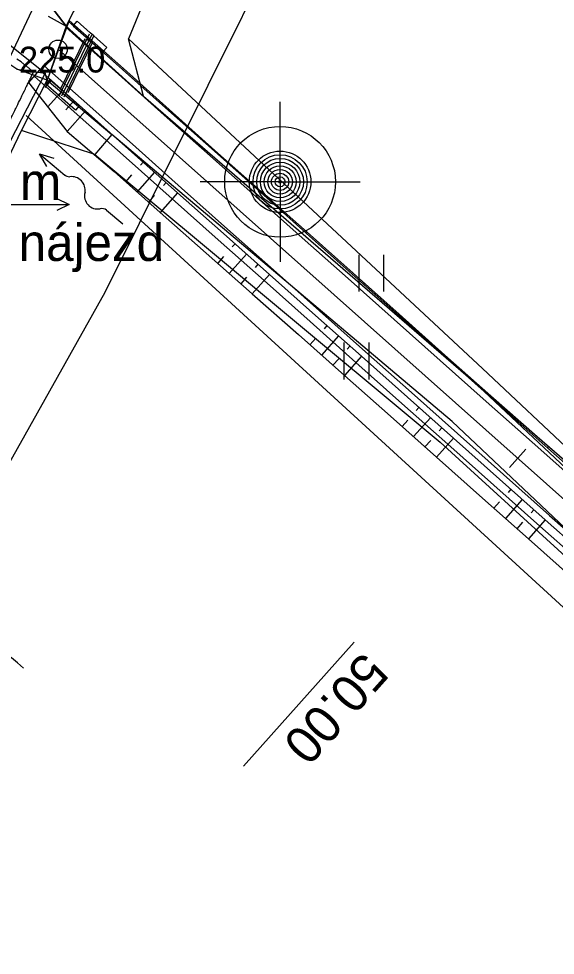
# Model space of a CAD drawing. Extents: x -495905 to -478420, y -1113297 to -1107716.
# Drawn here: x -480961.7 to -480918.1, y -1112652.6 to -1112576.5 of the extents above; entities that cross this region are included whole.
import ezdxf

# ---------------------------------------------------------------- set-up
doc = ezdxf.new("R2010")
doc.units = 0
for name, color, linetype in [('03_PC_OBJEKTY_NÁVRH_PR', 7, 'Continuous'), ('03_PC_OBJEKTY_STAV', 7, 'Continuous'), ('2D_VRSTEVNICE', 7, 'Continuous'), ('C13_HATCH_SLOPE_L', 7, 'Continuous'), ('C13_HATCH_SLOPE_R', 7, 'Continuous'), ('C13_HECTOMETRY', 7, 'Continuous'), ('C13_HLBODY', 7, 'Continuous'), ('C13_HRANA_TELESO', 7, 'Continuous'), ('C13_KORUNA', 7, 'Continuous'), ('C13_OSA', 7, 'Continuous'), ('C13_PRIKOP', 7, 'Continuous'), ('C13_STANICENI', 7, 'Continuous'), ('C13_VOZOVKA', 7, 'Continuous'), ('C13_ZPEVKRAJ', 7, 'Continuous'), ('DRENÁŽ', 7, 'Continuous'), ('ODVODNĚNÍ PLOŠNÉ', 7, 'Continuous'), ('PLYN', 7, 'Continuous'), ('VODNÍ PLOCHY', 7, 'Continuous'), ('VYRAZNE_VRST', 7, 'Continuous'), ('zamereni', 7, 'Continuous'), ('ŽLAB', 7, 'Continuous')]:
    doc.layers.add(name, color=color, linetype=linetype)

# ---------------------------------------------------------------- blocks, each defined once
blk = doc.blocks.new('A$C70B')
at = {"layer": 'DRENÁŽ'}
for p, q in [((0.869, 0.002), (-0.869, -0.002)), ((6.861, 0.426), (7.971, -0.002)), ((7.971, -0.002), (5.275, -0.002)), ((7.971, -0.002), (6.862, -0.478))]:
    blk.add_line(p, q, dxfattribs=at)
for centre, radius, start, end in [((0.872, 0.584), 0.582, 269.69241, 322.79009), ((2.168, -0.416), 1.055, 24.40393, 142.08362), ((4.08, 0.589), 1.109, 210.88731, 317.37071), ((5.319, -0.636), 0.636, 85.97658, 131.72478)]:
    blk.add_arc(centre, radius, start, end, dxfattribs=at)

msp = doc.modelspace()

# ---------------------------------------------------------------- linework, layer by layer
at = {"layer": '03_PC_OBJEKTY_NÁVRH_PR'}
msp.add_lwpolyline([(-480609.77, -1112943.11), (-480632.07, -1112906.22), (-480673.38, -1112848.12), (-480710, -1112791.67), (-480726.8, -1112776.25), (-480787.1, -1112736.87), (-480856.49, -1112680.15), (-480961.12, -1112584.33)], dxfattribs=at)
at = {"layer": '03_PC_OBJEKTY_STAV'}
msp.add_lwpolyline([(-480963.725, -1112582.338), (-480958.396, -1112571.03)], dxfattribs=at)
at = {"layer": '2D_VRSTEVNICE'}
msp.add_lwpolyline([(-480961.53, -1112579.991), (-480961.872, -1112579.756)], dxfattribs=at)
for points in [[(-480967, -1112594.132), (-480963.308, -1112586.491), (-480962.207, -1112584.3), (-480961.841, -1112583.543), (-480960.804, -1112581.405), (-480960.618, -1112581.033), (-480960.491, -1112580.772), (-480961.53, -1112579.991)], [(-480961.337, -1112629.24), (-480978.446, -1112614.383), (-480977.49, -1112614.89), (-480971.23, -1112602.397), (-480968.206, -1112596.513), (-480967, -1112594.132)]]:
    msp.add_open_spline(points, degree=2, dxfattribs=at)
at = {"layer": 'C13_HATCH_SLOPE_L'}
for p, q in [((-480957.024, -1112577.279), (-480956.956, -1112577.203)), ((-480956.09, -1112578.11), (-480956.054, -1112578.07)), ((-480955.157, -1112578.942), (-480955.081, -1112578.856)), ((-480954.223, -1112579.773), (-480954.183, -1112579.728)), ((-480953.289, -1112580.604), (-480953.205, -1112580.509)), ((-480948.621, -1112584.759), (-480948.593, -1112584.728)), ((-480948.565, -1112584.696), (-480948.565, -1112584.696)), ((-480947.687, -1112585.59), (-480947.633, -1112585.53)), ((-480946.753, -1112586.421), (-480946.728, -1112586.392)), ((-480946.702, -1112586.364), (-480946.702, -1112586.364)), ((-480945.82, -1112587.252), (-480945.77, -1112587.197)), ((-480941.151, -1112591.408), (-480941.121, -1112591.374)), ((-480941.091, -1112591.341), (-480941.091, -1112591.341)), ((-480940.218, -1112592.239), (-480940.152, -1112592.166)), ((-480939.213, -1112592.991), (-480939.213, -1112592.991)), ((-480939.284, -1112593.07), (-480939.248, -1112593.03)), ((-480938.35, -1112593.901), (-480938.274, -1112593.815)), ((-480933.682, -1112598.057), (-480933.646, -1112598.017)), ((-480933.611, -1112597.977), (-480933.611, -1112597.977)), ((-480932.748, -1112598.888), (-480932.68, -1112598.812)), ((-480931.814, -1112599.719), (-480931.782, -1112599.682)), ((-480931.749, -1112599.646), (-480931.749, -1112599.646)), ((-480930.881, -1112600.55), (-480930.818, -1112600.48)), ((-480926.212, -1112604.705), (-480926.186, -1112604.675)), ((-480926.159, -1112604.645), (-480926.159, -1112604.645)), ((-480925.278, -1112605.537), (-480925.223, -1112605.475)), ((-480924.345, -1112606.368), (-480924.316, -1112606.336)), ((-480924.288, -1112606.304), (-480924.288, -1112606.304)), ((-480923.411, -1112607.199), (-480923.353, -1112607.133)), ((-480918.641, -1112611.24), (-480918.641, -1112611.24)), ((-480918.743, -1112611.354), (-480918.692, -1112611.297))]:
    msp.add_line(p, q, dxfattribs=at)
at = {"layer": 'C13_HATCH_SLOPE_R'}
for p, q in [((-480960.016, -1112580.641), (-480960.918, -1112581.654)), ((-480959.082, -1112581.472), (-480959.607, -1112582.062)), ((-480958.149, -1112582.303), (-480959.346, -1112583.648)), ((-480957.215, -1112583.134), (-480957.888, -1112583.89)), ((-480956.281, -1112583.965), (-480957.775, -1112585.643)), ((-480951.613, -1112588.12), (-480951.834, -1112588.369)), ((-480952.546, -1112589.168), (-480953.035, -1112589.719)), ((-480950.679, -1112588.952), (-480952.101, -1112590.549)), ((-480949.745, -1112589.783), (-480949.966, -1112590.032)), ((-480948.812, -1112590.614), (-480950.233, -1112592.211)), ((-480950.678, -1112590.83), (-480951.167, -1112591.38)), ((-480944.143, -1112594.769), (-480944.364, -1112595.018)), ((-480945.069, -1112595.81), (-480945.552, -1112596.352)), ((-480943.209, -1112595.6), (-480944.615, -1112597.18)), ((-480942.276, -1112596.431), (-480942.498, -1112596.68)), ((-480943.199, -1112597.468), (-480943.679, -1112598.008)), ((-480941.342, -1112597.263), (-480942.743, -1112598.836)), ((-480936.674, -1112601.418), (-480936.896, -1112601.667)), ((-480937.588, -1112602.446), (-480938.06, -1112602.976)), ((-480935.74, -1112602.249), (-480937.124, -1112603.804)), ((-480934.806, -1112603.08), (-480935.027, -1112603.329)), ((-480935.718, -1112604.105), (-480936.188, -1112604.632)), ((-480933.873, -1112603.911), (-480935.252, -1112605.461)), ((-480929.204, -1112608.067), (-480929.426, -1112608.316)), ((-480928.27, -1112608.898), (-480929.642, -1112610.438)), ((-480930.11, -1112609.085), (-480930.574, -1112609.605)), ((-480927.337, -1112609.729), (-480927.558, -1112609.978)), ((-480928.244, -1112610.749), (-480928.709, -1112611.271)), ((-480926.403, -1112610.56), (-480927.777, -1112612.104)), ((-480921.735, -1112614.715), (-480921.956, -1112614.964)), ((-480922.644, -1112615.737), (-480923.11, -1112616.261)), ((-480920.801, -1112615.547), (-480922.176, -1112617.092)), ((-480919.867, -1112616.378), (-480920.088, -1112616.626)), ((-480918.933, -1112617.209), (-480920.308, -1112618.753)), ((-480920.776, -1112617.399), (-480921.242, -1112617.923))]:
    msp.add_line(p, q, dxfattribs=at)
at = {"layer": 'C13_HECTOMETRY'}
msp.add_circle((-480958.52, -1112578.96), 0.75, dxfattribs=at)
at = {"layer": 'C13_HLBODY'}
msp.add_circle((-480958.52, -1112578.96), 0.75, dxfattribs=at)
at = {"layer": 'C13_HRANA_TELESO'}
for p, q in [((-480957.626, -1112576.614), (-480959.4, -1112581.47)), ((-480957.626, -1112576.614), (-480953.205, -1112580.509)), ((-480953.205, -1112580.509), (-480949.496, -1112583.863)), ((-480960.918, -1112581.654), (-480957.775, -1112585.643)), ((-480949.496, -1112583.863), (-480945.77, -1112587.197)), ((-480957.775, -1112585.643), (-480953.969, -1112588.888)), ((-480945.77, -1112587.197), (-480942.03, -1112590.516)), ((-480953.969, -1112588.888), (-480950.233, -1112592.211)), ((-480942.03, -1112590.516), (-480938.274, -1112593.815)), ((-480950.233, -1112592.211), (-480946.488, -1112595.524)), ((-480938.274, -1112593.815), (-480934.542, -1112597.143)), ((-480946.488, -1112595.524), (-480942.742, -1112598.836)), ((-480934.542, -1112597.143), (-480930.818, -1112600.48)), ((-480942.742, -1112598.836), (-480938.997, -1112602.148)), ((-480930.818, -1112600.48), (-480927.094, -1112603.816)), ((-480938.997, -1112602.148), (-480935.252, -1112605.461)), ((-480927.094, -1112603.816), (-480923.353, -1112607.133)), ((-480935.252, -1112605.461), (-480931.506, -1112608.773)), ((-480923.353, -1112607.133), (-480919.584, -1112610.419)), ((-480931.506, -1112608.773), (-480927.777, -1112612.104)), ((-480919.584, -1112610.419), (-480915.814, -1112613.704)), ((-480927.777, -1112612.104), (-480924.044, -1112615.43)), ((-480924.044, -1112615.43), (-480920.308, -1112618.753)), ((-480920.308, -1112618.753), (-480916.572, -1112622.076))]:
    msp.add_line(p, q, dxfattribs=at)
at = {"layer": 'C13_KORUNA'}
for p, q in [((-480957.672, -1112576.703), (-480953.289, -1112580.604)), ((-480960.016, -1112580.641), (-480956.281, -1112583.965)), ((-480953.289, -1112580.604), (-480949.554, -1112583.928)), ((-480956.281, -1112583.965), (-480952.546, -1112587.289)), ((-480949.554, -1112583.928), (-480945.82, -1112587.252)), ((-480952.546, -1112587.289), (-480948.812, -1112590.614)), ((-480945.82, -1112587.252), (-480942.085, -1112590.577)), ((-480948.812, -1112590.614), (-480945.077, -1112593.938)), ((-480942.085, -1112590.577), (-480938.35, -1112593.901)), ((-480945.077, -1112593.938), (-480941.342, -1112597.263)), ((-480938.35, -1112593.901), (-480934.615, -1112597.226)), ((-480941.342, -1112597.263), (-480937.607, -1112600.587)), ((-480934.615, -1112597.226), (-480930.881, -1112600.55)), ((-480937.607, -1112600.587), (-480933.873, -1112603.911)), ((-480930.881, -1112600.55), (-480927.146, -1112603.874)), ((-480933.873, -1112603.911), (-480930.138, -1112607.236)), ((-480927.146, -1112603.874), (-480923.411, -1112607.199)), ((-480930.138, -1112607.236), (-480926.403, -1112610.56)), ((-480923.411, -1112607.199), (-480919.676, -1112610.523)), ((-480926.403, -1112610.56), (-480922.668, -1112613.884)), ((-480919.676, -1112610.523), (-480915.942, -1112613.847)), ((-480922.668, -1112613.884), (-480918.933, -1112617.209)), ((-480918.933, -1112617.209), (-480915.199, -1112620.533))]:
    msp.add_line(p, q, dxfattribs=at)
at = {"layer": 'C13_OSA'}
msp.add_line((-480958.52, -1112578.96), (-480855.083, -1112671.03), dxfattribs=at)
at = {"layer": 'C13_PRIKOP'}
for p, q in [((-480960.459, -1112581.138), (-480956.724, -1112584.463)), ((-480956.724, -1112584.463), (-480952.99, -1112587.787)), ((-480952.99, -1112587.787), (-480949.255, -1112591.112)), ((-480949.255, -1112591.112), (-480945.52, -1112594.436)), ((-480945.52, -1112594.436), (-480941.785, -1112597.76)), ((-480941.785, -1112597.76), (-480938.05, -1112601.085)), ((-480938.05, -1112601.085), (-480934.316, -1112604.409)), ((-480934.316, -1112604.409), (-480930.581, -1112607.733)), ((-480930.581, -1112607.733), (-480926.846, -1112611.058)), ((-480926.846, -1112611.058), (-480923.111, -1112614.382)), ((-480923.111, -1112614.382), (-480919.377, -1112617.707)), ((-480919.377, -1112617.707), (-480915.642, -1112621.031))]:
    msp.add_line(p, q, dxfattribs=at)
at = {"layer": 'C13_STANICENI'}
for p, q in [((-480921.837, -1112612.951), (-480920.507, -1112611.457)), ((-480934.47, -1112627.143), (-480943.446, -1112637.227))]:
    msp.add_line(p, q, dxfattribs=at)
at = {"layer": 'C13_VOZOVKA'}
for p, q in [((-480957.896, -1112577.173), (-480953.622, -1112580.977)), ((-480959.684, -1112580.267), (-480955.949, -1112583.592)), ((-480953.622, -1112580.977), (-480949.887, -1112584.302)), ((-480955.949, -1112583.592), (-480952.214, -1112586.916)), ((-480949.887, -1112584.302), (-480946.152, -1112587.626)), ((-480952.214, -1112586.916), (-480948.479, -1112590.24)), ((-480946.152, -1112587.626), (-480942.417, -1112590.95)), ((-480948.479, -1112590.24), (-480944.744, -1112593.565)), ((-480942.417, -1112590.95), (-480938.683, -1112594.275)), ((-480944.744, -1112593.565), (-480941.01, -1112596.889)), ((-480938.683, -1112594.275), (-480934.948, -1112597.599)), ((-480941.01, -1112596.889), (-480937.275, -1112600.213)), ((-480934.948, -1112597.599), (-480931.213, -1112600.923)), ((-480937.275, -1112600.213), (-480933.54, -1112603.538)), ((-480931.213, -1112600.923), (-480927.478, -1112604.248)), ((-480933.54, -1112603.538), (-480929.805, -1112606.862)), ((-480927.478, -1112604.248), (-480923.743, -1112607.572)), ((-480929.805, -1112606.862), (-480926.071, -1112610.187)), ((-480923.743, -1112607.572), (-480920.009, -1112610.897)), ((-480926.071, -1112610.187), (-480922.336, -1112613.511)), ((-480920.009, -1112610.897), (-480916.274, -1112614.221)), ((-480922.336, -1112613.511), (-480918.601, -1112616.835)), ((-480918.601, -1112616.835), (-480914.866, -1112620.16))]:
    msp.add_line(p, q, dxfattribs=at)
at = {"layer": 'C13_ZPEVKRAJ'}
for p, q in [((-480957.356, -1112577.653), (-480953.622, -1112580.977)), ((-480959.684, -1112580.267), (-480955.949, -1112583.592)), ((-480953.622, -1112580.977), (-480949.887, -1112584.302)), ((-480955.949, -1112583.592), (-480952.214, -1112586.916)), ((-480949.887, -1112584.302), (-480946.152, -1112587.626)), ((-480952.214, -1112586.916), (-480948.479, -1112590.24)), ((-480946.152, -1112587.626), (-480942.417, -1112590.95)), ((-480948.479, -1112590.24), (-480944.744, -1112593.565)), ((-480942.417, -1112590.95), (-480938.683, -1112594.275)), ((-480944.744, -1112593.565), (-480941.01, -1112596.889)), ((-480938.683, -1112594.275), (-480934.948, -1112597.599)), ((-480941.01, -1112596.889), (-480937.275, -1112600.213)), ((-480934.948, -1112597.599), (-480931.213, -1112600.923)), ((-480937.275, -1112600.213), (-480933.54, -1112603.538)), ((-480931.213, -1112600.923), (-480927.478, -1112604.248)), ((-480933.54, -1112603.538), (-480929.805, -1112606.862)), ((-480927.478, -1112604.248), (-480923.743, -1112607.572)), ((-480929.805, -1112606.862), (-480926.071, -1112610.187)), ((-480923.743, -1112607.572), (-480920.009, -1112610.897)), ((-480926.071, -1112610.187), (-480922.336, -1112613.511)), ((-480920.009, -1112610.897), (-480916.274, -1112614.221)), ((-480922.336, -1112613.511), (-480918.601, -1112616.835)), ((-480918.601, -1112616.835), (-480914.866, -1112620.16))]:
    msp.add_line(p, q, dxfattribs=at)
at = {"layer": 'ODVODNĚNÍ PLOŠNÉ'}
msp.add_lwpolyline([(-480567.113, -1112699.962), (-480605.769, -1112673.983), (-480643.576, -1112645.746), (-480678.366, -1112618.394), (-480715.87, -1112588.896), (-480749.353, -1112567.196), (-480787.892, -1112538.167), (-480825.553, -1112512.736), (-480861.397, -1112486.36), (-480890.78, -1112463.805), (-480913.927, -1112510.235), (-480932.387, -1112553.796), (-480954.714, -1112598.731), (-480984.471, -1112651.771), (-481010.43, -1112698.598)], dxfattribs=at)
at = {"layer": 'VODNÍ PLOCHY'}
for points in [[(-480918.44, -1112499.85), (-480920.82, -1112499.07), (-480921.52, -1112498.46), (-480923.69, -1112496.31), (-480930.63, -1112509.41), (-480944.75, -1112538.34), (-480944.17, -1112538.78), (-480950.8, -1112551.92), (-480961.54, -1112572.55), (-480962.3, -1112574.02), (-480960.09, -1112574.59), (-480959.37, -1112575.11), (-480957.86, -1112577.07), (-480939.63, -1112540.88), (-480918.44, -1112499.85)], [(-481000.75, -1112657.98), (-480998.67, -1112660.24), (-480990.49, -1112646.16), (-480961.49, -1112585.55), (-480959.4, -1112581.47), (-480961.88, -1112580.58), (-480962.68, -1112580.03), (-480964.34, -1112577.31), (-480971.56, -1112590.76), (-480992.13, -1112630.48), (-480999.29, -1112645.7), (-481004.08, -1112656.47), (-481001.4, -1112657.45), (-481000.75, -1112657.98)]]:
    msp.add_lwpolyline(points, dxfattribs=at)
at = {"layer": 'zamereni'}
for p, q in [((-480957.86, -1112577.07), (-480951.49, -1112564.66)), ((-480948, -1112566.37), (-480952.81, -1112578.12)), ((-480957.86, -1112577.07), (-480959.37, -1112575.11)), ((-480959.32, -1112576.27), (-480957.86, -1112577.07)), ((-480957.86, -1112577.07), (-480959.4, -1112581.47)), ((-480957.86, -1112577.07), (-480951.58, -1112582.76)), ((-480963.41, -1112577.85), (-480959.57, -1112580.9)), ((-480924.04, -1112604.91), (-480952.81, -1112578.12)), ((-480951.58, -1112582.76), (-480952.81, -1112578.12)), ((-480961.88, -1112580.58), (-480959.57, -1112580.9)), ((-480959.57, -1112580.9), (-480967.73, -1112596.73)), ((-480961.49, -1112585.55), (-480959.4, -1112581.47)), ((-480959.4, -1112581.47), (-480959.57, -1112580.9)), ((-480959.4, -1112581.47), (-480954.14, -1112585.88)), ((-480951.58, -1112582.76), (-480924.79, -1112605.94)), ((-480940.48, -1112589.73), (-480940.48, -1112583.23)), ((-480990.49, -1112646.16), (-480961.49, -1112585.55)), ((-480955.52, -1112587.52), (-480961.49, -1112585.55)), ((-480954.14, -1112585.88), (-480955.52, -1112587.52)), ((-480926.49, -1112609.22), (-480954.14, -1112585.88)), ((-480955.52, -1112587.52), (-480927.47, -1112610.89)), ((-480940.48, -1112589.73), (-480946.98, -1112589.73)), ((-480940.48, -1112589.73), (-480933.98, -1112589.73)), ((-480940.48, -1112589.73), (-480940.48, -1112596.23)), ((-480958.664, -1112591.05), (-480957.62, -1112591.56)), ((-480963.62, -1112591.56), (-480957.62, -1112591.56)), ((-480957.62, -1112591.56), (-480958.626, -1112592.06)), ((-480934.084, -1112595.65), (-480934.084, -1112598.65)), ((-480932.04, -1112598.65), (-480932.04, -1112595.65)), ((-480935.294, -1112602.79), (-480935.294, -1112605.79)), ((-480933.25, -1112605.79), (-480933.25, -1112602.79)), ((-480890.57, -1112636.32), (-480924.04, -1112604.91)), ((-480924.79, -1112605.94), (-480891.52, -1112637.2)), ((-480895.85, -1112638.14), (-480926.49, -1112609.22)), ((-480927.47, -1112610.89), (-480897.27, -1112638.49))]:
    msp.add_line(p, q, dxfattribs=at)
for radius in [4.5, 2.5, 2.2, 1.9, 1.9, 1.6, 1.3, 1, 0.7, 0.4, 0.1]:
    msp.add_circle((-480940.48, -1112589.73), radius, dxfattribs=at)
at = {"layer": 'ŽLAB'}
for p, q in [((-480957.29, -1112577.06), (-480956.96, -1112576.686)), ((-480955.91, -1112577.612), (-480956.96, -1112576.686)), ((-480957.29, -1112577.06), (-480956.241, -1112577.987)), ((-480955.994, -1112577.719), (-480956.432, -1112578.618)), ((-480955.61, -1112577.877), (-480955.91, -1112577.612)), ((-480958.416, -1112582.688), (-480956.213, -1112578.168)), ((-480956.348, -1112578.102), (-480958.331, -1112582.172)), ((-480955.815, -1112577.806), (-480958.236, -1112582.775)), ((-480955.635, -1112577.894), (-480958.056, -1112582.863)), ((-480957.702, -1112582.479), (-480955.719, -1112578.409)), ((-480955.854, -1112578.343), (-480956.213, -1112578.168)), ((-480955.635, -1112577.894), (-480956.073, -1112578.793)), ((-480955.941, -1112578.252), (-480954.891, -1112579.178)), ((-480954.56, -1112578.803), (-480955.61, -1112577.877)), ((-480954.891, -1112579.178), (-480954.56, -1112578.803)), ((-480959.179, -1112581.423), (-480959.508, -1112581.8)), ((-480959.179, -1112581.423), (-480958.125, -1112582.345)), ((-480958.454, -1112582.721), (-480959.508, -1112581.8)), ((-480958.196, -1112582.238), (-480958.415, -1112582.687)), ((-480958.153, -1112582.985), (-480958.454, -1112582.721)), ((-480957.099, -1112583.906), (-480958.153, -1112582.985)), ((-480957.837, -1112582.413), (-480958.056, -1112582.863)), ((-480957.824, -1112582.608), (-480956.77, -1112583.53)), ((-480956.77, -1112583.53), (-480957.099, -1112583.906))]:
    msp.add_line(p, q, dxfattribs=at)

# ---------------------------------------------------------------- block references
at = {"layer": 'PLYN', "rotation": 139.82273357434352}
msp.add_blockref('A$C70B', (-480953.927, -1112592.598), dxfattribs=at)

# ---------------------------------------------------------------- texts
at = {"layer": 'C13_STANICENI'}
msp.add_text('50.00', height=3, rotation=228.32731, dxfattribs=at).set_placement((-480933.722, -1112627.807))
at = {"layer": 'VYRAZNE_VRST'}
msp.add_text(' 225.0', height=2.1, dxfattribs=at).set_placement((-480962.485, -1112580.848))
msp.add_text(' 225.0', height=2.1, dxfattribs=at).set_placement((-480962.485, -1112580.848))
at = {"layer": 'zamereni'}
for s, p in [('0,3 m', (-480968.298, -1112591.21)), ('nájezd', (-480961.724, -1112596.16))]:
    msp.add_text(s, height=3, dxfattribs=at).set_placement(p)

doc.saveas('drawing.dxf')
